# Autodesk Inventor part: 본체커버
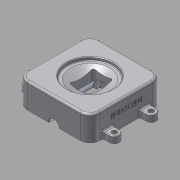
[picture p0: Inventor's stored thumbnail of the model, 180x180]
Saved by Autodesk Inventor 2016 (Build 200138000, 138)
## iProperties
Created: 2018-01
Part Number: 본체커버
Material: 알루미늄 6061
Document SubType Name: Modeling
Designer: mduedu
Density: 1 g/cm^3
Appearance: 알루미늄 - 평지
Author: mduedu
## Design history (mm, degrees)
sketch "스케치1"
  geometry: L1 (55, 55)-(-55, 55); L2 (-55, 55)-(-55, -55); L3 (-55, -55)-(55, -55); L4 (55, -55)-(55, 55); L5 (55, 55)-(-55, -55); L6 (-55, 55)-(55, -55); 1 further point
  constraints: 12 end point, 2 midpoint, 2 parallel, 1 horizontal, 1 perpendicular
  dimensions: "d0" = 110 distance of L3.end L2.end; "d1" = 110 distance of L2.end L1.end
extrude "돌출1" new body sketch "스케치1" distance "d2" = 38; taper "d3" = 0 deg
sketch "스케치2"
  geometry: L1 (-55, 55)-(55, 55) reference; L2 (-55, -55)-(-55, 55) reference; L3 (55, -55)-(-55, -55) reference; L4 (55, 55)-(55, -55) reference; L5 (0, 55)-(7.5, 55); L6 (7.5, 55)-(7.5, 36); L7 (7.5, 36)-(0, 36); L8 (0, 36)-(0, 55); L9 (0, 36)-(16, 36); L10 (16, 36)-(16, 22); L11 (16, 22)-(0, 22); L12 (0, 22)-(0, 36); L13 (0, 22)-(20, 22); L14 (20, 22)-(20, -25); L15 (20, -25)-(0, -25); L16 (0, -25)-(0, 22); L17 (0, -25)-(15, -25); L18 (15, -25)-(15, -30); L19 (15, -30)-(0, -30); L20 (0, -30)-(0, -25); 1 further point
  constraints: 32 end point, 8 parallel, 4 horizontal, 4 perpendicular, 1 midpoint
  dimensions: "d4" = 15 diameter of L6 L8; "d6" = 32 diameter of L10 L12; "d7" = 40 diameter of L14 L16; "d8" = 30 diameter of L18 L20; "d9" = 5 distance of L17.end L18.end; "d10" = 47 distance of L13.end L14.end; "d11" = 14 distance of L9.end L10.end; "d12" = 19 distance of L5.end L6.end
revolve "회전1" sketch "스케치2" stored, may be unused: angle "d13" = 90 deg
fillet "모깎기1" dims "d14" = 1
fillet "모깎기2" dims "d15" = 15
fillet "모깎기3" dims "d16" = 3
sketch "스케치3"
  geometry: L1 (-15, -17)-(15, -17); L2 (15, -17)-(15, 20); L3 (15, 20)-(-15, 20); L4 (-15, 20)-(-15, -17); L5 (-19, -22)-(19, -22) reference; L6 (19, 25)-(-19, 25) reference; 2 further points
  constraints: 8 end point, 2 parallel, 1 horizontal, 1 midpoint, 1 perpendicular, 1 vertical alignment
  dimensions: "d17" = 5 distance between parallel lines of L1 L5; "d18" = 5 distance between parallel lines of L6 L3; "d19" = 37 distance of L3.end L1.start (derived); "d20" = 30 distance between parallel lines of L2 L4
extrude "돌출2" cut sketch "스케치3" stored distance "d21" = 38; taper "d22" = 0 deg
fillet "모깎기4" dims "d23" = 3
sketch "스케치4"
  geometry: L1 (38, 35)-(33, 35); L2 (33, 35)-(33, 30); L3 (33, 30)-(26, 15); L4 (26, 15)-(26, 0); L5 (26, 0)-(38, 0); L6 (38, 0)-(38, 35); L7 (38, 40)-(38, -40) reference; 1 further point
  constraints: 12 end point, 2 parallel, 1 collinear, 1 horizontal, 1 horizontal alignment, 1 perpendicular
  dimensions: "d24" = 5 distance of L1.start L1.end; "d26" = 70 diameter of L1 L5; "d28" = 60 diameter of L2.end L5; "d29" = 30 diameter of L3.end L5; "d30" = 7 horizontal distance of L2.end L3.end
revolve "회전2" sketch "스케치4" stored, may be unused: angle "d31" = 90 deg
chamfer "모따기1" distance "d32" = 1; stored, may be unused: second distance "d33" = 2, angle "d34" = 45 deg
fillet "모깎기5" dims "d35" = 1
chamfer "모따기2" distance "d36" = 1; stored, may be unused: second distance "d37" = 2, angle "d38" = 45 deg
sketch "스케치5"
  geometry: L1 (7.5, 54)-(8.5, 55) reference; L2 (7.5, 54)-(7.5, 37) reference; L3 (8.5, 36)-(7.5, 37) reference; L4 (8.5, 36)-(15, 36) reference; L5 (16, 35)-(16, 22) reference; L6 (16, 22)-(19, 22) reference; L7 (20, 21)-(20, -24) reference; L8 (19, -25)-(15, -25) reference; L9 (15, -25)-(15, -29) reference; L10 (14, -30)-(-14, -30) reference; L11 (-15, -29)-(-15, -25) reference; L12 (-15, -25)-(-19, -25) reference; L13 (-20, -24)-(-20, 21) reference; L14 (-19, 22)-(-16, 22) reference; L15 (-16, 22)-(-16, 35) reference; L16 (-15, 36)-(-8.5, 36) reference; L17 (-7.5, 37)-(-8.5, 36) reference; L18 (-7.5, 37)-(-7.5, 54) reference; L19 (-8.5, 55)-(-7.5, 54) reference; L20 (-40, 55)-(-8.5, 55) reference; L21 (-55, -40)-(-55, 40) reference; L22 (40, -55)-(-40, -55) reference; L23 (55, 40)-(55, -40) reference; L24 (8.5, 55)-(40, 55) reference; L25 (55, 35.5)-(65, 35.5); L26 (65, 20.5)-(55, 20.5); L27 (55, 20.5)-(55, 35.5); L28 (55, 40)-(55, -40) reference; A1 r 1 centre (15, 35) between (16, 35) and (15, 36) reference; A2 r 1 centre (19, 21) between (20, 21) and (19, 22) reference; A3 r 1 centre (19, -24) between (19, -25) and (20, -24) reference; A4 r 1 centre (14, -29) between (14, -30) and (15, -29) reference; A5 r 1 centre (-14, -29) between (-15, -29) and (-14, -30) reference; A6 r 1 centre (-19, -24) between (-20, -24) and (-19, -25) reference; A7 r 1 centre (-19, 21) between (-19, 22) and (-20, 21) reference; A8 r 1 centre (-15, 35) between (-15, 36) and (-16, 35) reference; A9 r 15 centre (-40, 40) between (-40, 55) and (-55, 40) reference; A10 r 15 centre (-40, -40) between (-55, -40) and (-40, -55) reference; A11 r 15 centre (40, -40) between (40, -55) and (55, -40) reference; A12 r 15 centre (40, 40) between (55, 40) and (40, 55) reference; A13 r 7.5 centre (65, 28) between (65, 20.5) and (65, 35.5); 1 further point
  constraints: 6 end point, 2 point on circle, 2 tangent, 1 centre point, 1 collinear, 1 horizontal, 1 parallel, 1 point on line
  dimensions: "d39" = 15 distance between parallel lines of L26 L25; "d41" = 28 vertical distance of A13.centre point (0, 0); "d42" = 10 distance from line of A13.centre L23
extrude "돌출3" join sketch "스케치5" distance "d43" = 10; taper "d44" = 0 deg
fillet "모깎기6" dims "d45" = 1
fillet "모깎기7" dims "d46" = 3
sketch "스케치6"
  geometry: A1 r 7.5 centre (-65, 28) between (-65, 35.5) and (-65, 20.5) reference; A2 r 7.5 centre (-65, -28) between (-65, -20.5) and (-65, -35.5) reference; A3 r 7.5 centre (65, -28) between (65, -35.5) and (65, -20.5) reference; A4 r 7.5 centre (65, 28) between (65, 20.5) and (65, 35.5) reference; 5 further points
  constraints: 4 coincident
sketch "스케치7"
  geometry: 4 further points
  constraints: 4 other
hole "구멍1" sketch "스케치7" at (-65, 28), (65, 28), (-65, -28), (65, -28) diameter "d47" = 4.5; stored, may be unused: countersink angle "d51" = 90 deg, drill point angle "d53" = 0 deg; dims "d48" = 6, "d49" = 8, "d50" = 4.6, "d52" = 8
sketch "스케치8"
  geometry: L1 (-95, 35)-(-95, 0) reference; L2 (0, 38)-(-80, 38) reference; 2 further points
  constraints: 1 other
  dimensions: "d54" = 55 distance from line of point (-40, 23) L1; "d55" = 15 distance from line of point (-40, 23) L2
feature "엠보싱1" sketch "스케치8" dims "d0" = 110, "d1" = 110, "d56" = 0.5, "d57" = 0
node "솔리드1"
mirror "대칭1"
mirror "대칭2"
node "투영된 루프1"
node "투영된 루프2"
